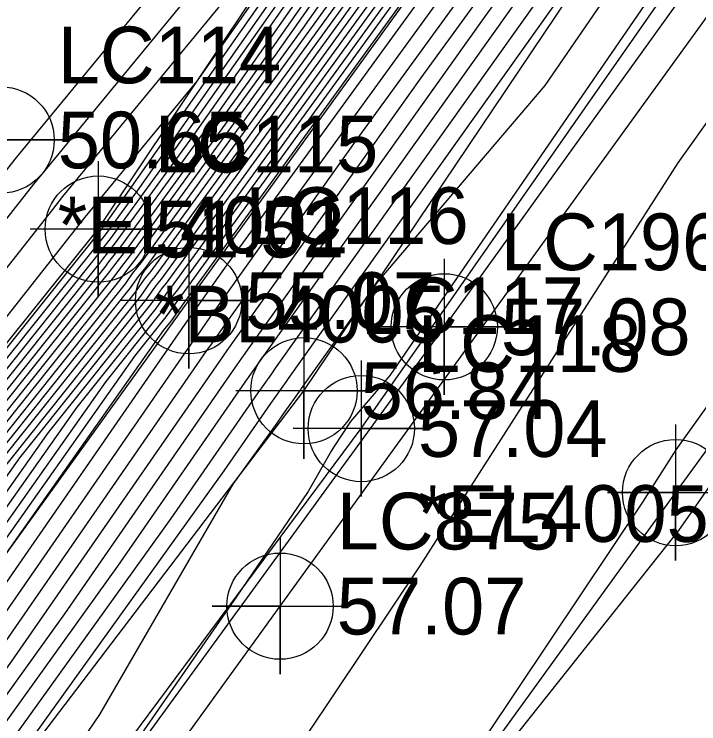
# Model space of a CAD drawing. Extents: x 2188792 to 2191981, y 386090 to 389710.
# Drawn here: x 2190020.33 to 2190050.53, y 387484.06 to 387515.36 of the extents above; entities that cross this region are included whole.
import ezdxf

# ---------------------------------------------------------------- set-up
doc = ezdxf.new("R2010")
doc.units = 0
for name, color, linetype in [('DTM Contours Major', 7, 'Continuous'), ('DTM Contours Minor', 7, 'Continuous'), ('Exist DTM Breakline', 7, 'Continuous'), ('Exist DTM Breakline Cogo Comment', 7, 'Continuous'), ('Exist DTM Breakline Cogo Elevation', 7, 'Continuous'), ('Exist DTM Breakline Cogo Number', 7, 'Continuous'), ('Exist DTM Breakline Cogo Point CELL', 7, 'Continuous'), ('Exist DTM Regular Point Underwater CELL', 7, 'Continuous'), ('Exist DTM Regular Point Underwater Cogo Comment', 7, 'Continuous'), ('Exist DTM Regular Point Underwater Cogo Elevation', 7, 'Continuous'), ('Exist DTM Regular Point Underwater Cogo Number', 7, 'Continuous'), ('Exist Roads EOP', 7, 'Continuous'), ('Exist Roads EOP Cogo Elevation', 7, 'Continuous'), ('Exist Roads EOP Cogo Number', 7, 'Continuous'), ('Exist Roads EOP Cogo Point CELL', 7, 'Continuous'), ('Exist Roads EOT', 7, 'Continuous'), ('Exist Roads EOT Cogo Elevation', 7, 'Continuous'), ('Exist Roads EOT Cogo Number', 7, 'Continuous'), ('Exist Roads EOT Cogo Point CELL', 7, 'Continuous')]:
    doc.layers.add(name, color=color, linetype=linetype)

msp = doc.modelspace()

# ---------------------------------------------------------------- linework, layer by layer
at = {"layer": 'DTM Contours Major'}
for points in [[(2189984.352, 387440.029), (2189988.632, 387446.331), (2189991.161, 387450.388), (2189992.862, 387452.939), (2190007.704, 387474.081), (2190010.026, 387477.237), (2190010.866, 387478.407), (2190020.031, 387491.642), (2190026.918, 387501.402), (2190027.261, 387501.831), (2190027.928, 387502.771), (2190027.942, 387502.789), (2190045.269, 387526.683), (2190045.546, 387527.079), (2190062.971, 387551.105)], [(2189957.921, 387412.608), (2189960.495, 387415.615), (2189963.565, 387419.576), (2189966.033, 387422.473), (2189971.823, 387427.618), (2189973.953, 387429.864), (2189975.86, 387430.935), (2189976.679, 387433.44), (2189978.768, 387435.688), (2189981.855, 387440.257), (2189983.77, 387442.845), (2189986.732, 387447.206), (2189989.796, 387452.121), (2189990.78, 387454.257), (2190003.512, 387472.407), (2190008.404, 387478.538), (2190020.573, 387495.783), (2190026.132, 387502.74), (2190026.608, 387503.41), (2190026.821, 387503.676), (2190039.173, 387520.711), (2190044.314, 387528.031), (2190057.303, 387545.941)], [(2189957.493, 387397.732), (2189959.964, 387401.028), (2189969.853, 387414.121), (2189972.085, 387417.1), (2189976.117, 387420.341), (2189977.065, 387420.694), (2189985.076, 387432.063), (2189985.095, 387433.258), (2189987.112, 387436.647), (2189989.644, 387440.904), (2189993.471, 387446.692), (2189993.574, 387448.499), (2189995.205, 387451.102), (2190002.478, 387461.302), (2190012.599, 387475.058), (2190022.556, 387488.916), (2190029.949, 387499.592), (2190030.371, 387500.182), (2190030.688, 387500.641), (2190041.096, 387515.254), (2190048.167, 387524.986), (2190060.341, 387542.129)], [(2190065.584, 387541.202), (2190052.374, 387521.969), (2190036.892, 387499.429), (2190035.158, 387497.397), (2190034.428, 387496.276), (2190034.315, 387496.082), (2190033.287, 387494.306), (2190030.14, 387489.689), (2190021.316, 387476.946), (2190020.217, 387475.365), (2190016.872, 387468.628), (2190016.421, 387467.617), (2190003.679, 387446.83), (2190000.724, 387442.025), (2189990.894, 387427.571), (2189987.772, 387422.404), (2189976.242, 387405.344), (2189970.251, 387398.185), (2189960.836, 387388.027), (2189958.804, 387385.627)], [(2189955.068, 387412.785), (2189960.286, 387418.879), (2189961.085, 387419.91), (2189965.998, 387425.677), (2189967.889, 387427.358), (2189972.645, 387432.374), (2189973.523, 387432.867), (2189973.901, 387434.022), (2189978.006, 387438.439), (2189979.705, 387440.954), (2189983.189, 387445.661), (2189984.832, 387448.081), (2189986.532, 387450.808), (2189988.83, 387455.794), (2189996.597, 387466.866), (2190006.879, 387479.75), (2190014.228, 387490.164), (2190025.003, 387503.648), (2190025.288, 387504.048), (2190025.699, 387504.563), (2190033.078, 387514.739), (2190043.082, 387528.982), (2190051.636, 387540.776)], [(2189957.168, 387450.113), (2189962.705, 387455.58), (2189963.359, 387456.976), (2189968.321, 387461.932), (2189971.382, 387462.319), (2189982.029, 387462.255), (2189993.359, 387476.866), (2189994.6, 387481.754), (2189995.932, 387520.719), (2190013.29, 387497.82), (2190021.199, 387507.858), (2190021.483, 387508.219), (2190037.161, 387527.264), (2190028.053, 387532.529), (2190026.213, 387539.316)], [(2189953.618, 387431.202), (2189959.565, 387434.157), (2189961.984, 387436.074), (2189969.442, 387436.668), (2189973.707, 387437.385), (2189977.243, 387441.19), (2189977.555, 387441.65), (2189982.607, 387448.477), (2189982.933, 387448.956), (2189983.269, 387449.495), (2189986.88, 387457.33), (2189989.682, 387461.324), (2190005.354, 387480.961), (2190007.883, 387484.545), (2190023.875, 387504.556), (2190023.967, 387504.687), (2190024.577, 387505.45), (2190026.983, 387508.767), (2190041.85, 387529.933), (2190045.968, 387535.612)]]:
    msp.add_lwpolyline(points, dxfattribs=at)
at = {"layer": 'DTM Contours Minor'}
for points in [[(2189958.048, 387448.514), (2189959.221, 387449.811), (2189963.913, 387454.444), (2189963.96, 387454.544), (2189969.838, 387460.415), (2189970.296, 387460.473), (2189983.751, 387460.392), (2189998.07, 387478.857), (2189998.788, 387481.688), (2189999.56, 387504.257), (2190009.614, 387490.994), (2190022.026, 387506.747), (2190022.471, 387507.313), (2190035.891, 387523.615), (2190040.864, 387530.695), (2190041.434, 387531.48), (2190058.134, 387555.179)], [(2189955.119, 387438.452), (2189959.956, 387442.286), (2189963.705, 387442.584), (2189971.264, 387443.854), (2189972.973, 387445.744), (2189977.203, 387450.649), (2189978.807, 387452.419), (2189984.064, 387453.528), (2189986.1, 387457.945), (2189986.916, 387459.108), (2190004.744, 387481.446), (2190005.345, 387482.298), (2190023.423, 387504.92), (2190023.439, 387504.943), (2190024.129, 387505.805), (2190024.545, 387506.379), (2190041.357, 387530.314), (2190043.701, 387533.546), (2190058.663, 387554.778)], [(2189958.943, 387445.392), (2189960.837, 387445.543), (2189964.656, 387446.184), (2189968.309, 387450.223), (2189970.339, 387452.577), (2189974.036, 387456.657), (2189982.989, 387458.545), (2189985.473, 387458.53), (2190002.78, 387480.847), (2190002.977, 387481.622), (2190003.188, 387487.795), (2190005.938, 387484.167), (2190022.852, 387505.635), (2190023.46, 387506.407), (2190028.397, 387512.404), (2190041.111, 387530.504), (2190042.568, 387532.513), (2190058.398, 387554.979)], [(2189957.342, 387436.305), (2189960.97, 387439.18), (2189966.574, 387439.626), (2189976.709, 387441.329), (2189977.091, 387441.74), (2189977.125, 387441.79), (2189982.491, 387449.04), (2189982.553, 387449.13), (2189982.616, 387449.233), (2189986.49, 387457.637), (2189988.299, 387460.216), (2190005.049, 387481.204), (2190006.614, 387483.421), (2190023.649, 387504.738), (2190023.703, 387504.815), (2190024.353, 387505.628), (2190025.764, 387507.573), (2190041.603, 387530.124), (2190044.835, 387534.579), (2190058.927, 387554.577)], [(2189955.308, 387371.872), (2189966.747, 387385.386), (2189969.936, 387388.826), (2189985.972, 387407.987), (2189987.388, 387410.082), (2189997.235, 387426.377), (2190000.201, 387430.738), (2190011.219, 387448.654), (2190017.983, 387459.688), (2190025.097, 387470.227), (2190031.989, 387481.689), (2190038.237, 387491.023), (2190049.61, 387508.8), (2190053.061, 387513.633), (2190063.181, 387529.704), (2190065.491, 387532.944), (2190080.791, 387553.075)], [(2189955.863, 387403.686), (2189960.537, 387409.923), (2189962.716, 387412.808), (2189967.226, 387418.828), (2189975.374, 387425.378), (2189977.291, 387426.092), (2189980.462, 387430.593), (2189980.5, 387432.909), (2189983.924, 387438.665), (2189984.435, 387439.422), (2189984.468, 387439.466), (2189989.012, 387446.156), (2189990.295, 387448.214), (2189993.358, 387452.805), (2190003.177, 387466.793), (2190010.541, 387476.802), (2190013.204, 387480.508), (2190027.711, 387501.458), (2190027.772, 387501.543), (2190028.391, 387502.438), (2190029.827, 387504.455), (2190046.003, 387526.716), (2190047.848, 387529.313), (2190063.603, 387551)], [(2189956.27, 387402.198), (2189960.394, 387407.699), (2189964.5, 387413.136), (2189968.441, 387418.396), (2189975.56, 387424.119), (2189977.234, 387424.742), (2189981.616, 387430.96), (2189981.649, 387432.997), (2189985.085, 387438.773), (2189989.245, 387445.764), (2189989.392, 387445.981), (2189989.429, 387446.041), (2189993.853, 387452.672), (2189998.65, 387459.506), (2190011.055, 387476.366), (2190015.542, 387482.61), (2190028.271, 387500.992), (2190028.421, 387501.203), (2190028.965, 387501.988), (2190032.644, 387507.154), (2190046.544, 387526.283), (2190050.971, 387532.517), (2190064.1, 387550.59)], [(2189984.235, 387440.592), (2189988.252, 387446.506), (2189992.027, 387452.562), (2189992.367, 387453.072), (2189997.801, 387460.812), (2190009.043, 387476.841), (2190009.625, 387477.569), (2190025.649, 387500.279), (2190027.035, 387502.013), (2190027.664, 387502.899), (2190027.718, 387502.967), (2190044.05, 387525.489), (2190045.3, 387527.269), (2190061.837, 387550.072)], [(2189955.19, 387406.762), (2189959.632, 387412.503), (2189960.621, 387413.657), (2189965.053, 387419.376), (2189966.055, 387420.551), (2189974.184, 387427.774), (2189974.737, 387428.358), (2189977.262, 387429.776), (2189978.346, 387433.091), (2189979.225, 387434.037), (2189983.145, 387439.839), (2189984.119, 387441.155), (2189987.872, 387446.681), (2189991.754, 387452.908), (2189991.95, 387453.335), (2190007.66, 387475.732), (2190009.32, 387477.811), (2190024.38, 387499.155), (2190026.81, 387502.195), (2190027.4, 387503.027), (2190027.494, 387503.144), (2190042.83, 387524.295), (2190045.054, 387527.46), (2190060.704, 387549.039)], [(2190066.588, 387548.537), (2190049.25, 387524.121), (2190046.73, 387520.654), (2190031.837, 387499.742), (2190031.67, 387499.501), (2190031.068, 387498.659), (2190027.232, 387493.119), (2190013.629, 387474.186), (2190010.451, 387469.867), (2190000.703, 387456.196), (2189998.289, 387452.392), (2189996.348, 387449.596), (2189996.21, 387447.174), (2189989.807, 387437.489), (2189988.463, 387435.23), (2189987.393, 387433.432), (2189987.383, 387432.798), (2189976.952, 387417.995), (2189976.488, 387417.822), (2189974.514, 387416.236), (2189973.422, 387414.778), (2189959.678, 387396.581), (2189958.309, 387394.755)], [(2189955.108, 387407.428), (2189959.062, 387412.538), (2189960.579, 387414.31), (2189964.557, 387419.443), (2189966.047, 387421.192), (2189973.397, 387427.722), (2189974.476, 387428.86), (2189976.795, 387430.162), (2189977.791, 387433.208), (2189979.072, 387434.587), (2189982.715, 387439.979), (2189984.003, 387441.719), (2189987.492, 387446.856), (2189991.101, 387452.646), (2189991.56, 387453.643), (2190006.277, 387474.624), (2190009.014, 387478.054), (2190023.111, 387498.031), (2190026.584, 387502.376), (2190027.136, 387503.154), (2190027.269, 387503.321), (2190041.611, 387523.1), (2190044.807, 387527.65), (2190059.57, 387548.006)], [(2190067.418, 387547.671), (2190051.466, 387526.048), (2190049.791, 387523.688), (2190049.547, 387523.353), (2190032.412, 387499.293), (2190032.32, 387499.161), (2190031.628, 387498.193), (2190029.57, 387495.221), (2190015.34, 387475.415), (2190014.879, 387474.621), (2190014.239, 387473.68), (2190005.531, 387459.96), (2189997.647, 387448.599), (2189997.579, 387447.415), (2189989.888, 387435.781), (2189989.138, 387434.522), (2189988.542, 387433.519), (2189988.536, 387433.165), (2189976.896, 387416.646), (2189976.674, 387416.563), (2189975.729, 387415.804), (2189975.206, 387415.106), (2189959.534, 387394.357), (2189958.717, 387393.266)], [(2189958.491, 387412.573), (2189960.537, 387414.962), (2189964.061, 387419.509), (2189966.04, 387421.833), (2189972.61, 387427.67), (2189974.214, 387429.362), (2189976.327, 387430.549), (2189977.235, 387433.324), (2189978.92, 387435.137), (2189982.285, 387440.118), (2189983.887, 387442.282), (2189987.112, 387447.031), (2189990.448, 387452.383), (2189991.17, 387453.95), (2190004.894, 387473.516), (2190008.709, 387478.296), (2190021.842, 387496.907), (2190026.358, 387502.558), (2190026.872, 387503.282), (2190027.045, 387503.499), (2190040.392, 387521.906), (2190044.561, 387527.84), (2190058.437, 387546.974)], [(2190068.248, 387546.805), (2190057.272, 387531.926), (2190051.04, 387522.853), (2190043.736, 387512.22), (2190036.345, 387503.56), (2190032.986, 387498.844), (2190032.97, 387498.82), (2190032.188, 387497.726), (2190031.908, 387497.323), (2190029.977, 387494.635), (2190024.083, 387484.464), (2190015.878, 387472.42), (2190012.773, 387467.529), (2190000.192, 387449.398), (2189999.383, 387448.234), (2189997.616, 387445.64), (2189989.969, 387434.074)], [(2189957.901, 387396.243), (2189959.821, 387398.805), (2189971.637, 387414.449), (2189973.299, 387416.668), (2189976.302, 387419.082), (2189977.009, 387419.345), (2189986.229, 387432.43), (2189986.244, 387433.345), (2189987.787, 387435.939), (2189989.725, 387439.197), (2189994.84, 387446.933), (2189994.978, 387449.349), (2189995.635, 387450.396), (2190006.465, 387465.585), (2190013.114, 387474.622), (2190024.894, 387491.018), (2190030.509, 387499.126), (2190031.021, 387499.841), (2190031.263, 387500.191), (2190043.913, 387517.954), (2190048.709, 387524.553), (2190063.465, 387545.333)], [(2189957.35, 387412.644), (2189960.453, 387416.268), (2189963.069, 387419.643), (2189966.026, 387423.114), (2189971.037, 387427.566), (2189973.691, 387430.366), (2189975.393, 387431.321), (2189976.124, 387433.557), (2189978.615, 387436.238), (2189981.425, 387440.397), (2189983.654, 387443.408), (2189986.352, 387447.381), (2189989.143, 387451.858), (2189990.39, 387454.565), (2190002.129, 387471.299), (2190008.099, 387478.781), (2190019.304, 387494.66), (2190025.906, 387502.921), (2190026.344, 387503.538), (2190026.596, 387503.854), (2190037.954, 387519.517), (2190044.068, 387528.221), (2190056.17, 387544.908)], [(2189956.78, 387412.679), (2189960.412, 387416.92), (2189962.573, 387419.71), (2189966.019, 387423.755), (2189970.25, 387427.514), (2189973.429, 387430.868), (2189974.925, 387431.708), (2189975.568, 387433.673), (2189978.463, 387436.788), (2189980.995, 387440.536), (2189983.538, 387443.971), (2189985.972, 387447.556), (2189988.49, 387451.595), (2189990, 387454.872), (2190000.746, 387470.191), (2190007.794, 387479.023), (2190018.035, 387493.536), (2190025.681, 387503.103), (2190026.08, 387503.665), (2190026.372, 387504.031), (2190036.735, 387518.323), (2190043.821, 387528.411), (2190055.036, 387543.875)], [(2189956.209, 387412.714), (2189960.37, 387417.573), (2189962.077, 387419.776), (2189966.012, 387424.396), (2189969.463, 387427.462), (2189973.168, 387431.37), (2189974.458, 387432.094), (2189975.012, 387433.789), (2189978.31, 387437.338), (2189980.565, 387440.675), (2189983.421, 387444.534), (2189985.592, 387447.731), (2189987.838, 387451.333), (2189989.61, 387455.179), (2189999.363, 387469.082), (2190007.489, 387479.265), (2190016.766, 387492.412), (2190025.455, 387503.285), (2190025.816, 387503.793), (2190026.148, 387504.208), (2190035.516, 387517.128), (2190043.575, 387528.601), (2190053.903, 387542.842)], [(2189955.639, 387412.749), (2189960.328, 387418.226), (2189961.581, 387419.843), (2189966.005, 387425.036), (2189968.676, 387427.41), (2189972.906, 387431.872), (2189973.991, 387432.481), (2189974.457, 387433.906), (2189978.158, 387437.888), (2189980.135, 387440.815), (2189983.305, 387445.098), (2189985.212, 387447.906), (2189987.185, 387451.07), (2189989.22, 387455.486), (2189997.98, 387467.974), (2190007.184, 387479.507), (2190015.497, 387491.288), (2190025.229, 387503.466), (2190025.552, 387503.921), (2190025.923, 387504.386), (2190034.297, 387515.934), (2190043.329, 387528.792), (2190052.769, 387541.809)], [(2189954.498, 387412.82), (2189960.244, 387419.531), (2189960.589, 387419.977), (2189965.991, 387426.318), (2189967.102, 387427.306), (2189972.383, 387432.876), (2189973.056, 387433.254), (2189973.345, 387434.138), (2189977.853, 387438.989), (2189979.275, 387441.093), (2189983.073, 387446.224), (2189984.452, 387448.256), (2189985.88, 387450.545), (2189988.44, 387456.101), (2189995.214, 387465.757), (2190006.574, 387479.992), (2190012.959, 387489.04), (2190024.778, 387503.83), (2190025.024, 387504.176), (2190025.475, 387504.741), (2190031.859, 387513.545), (2190042.836, 387529.172), (2190050.502, 387539.743)], [(2189957.086, 387399.221), (2189960.107, 387403.252), (2189968.069, 387413.793), (2189970.87, 387417.532), (2189975.931, 387421.6), (2189977.121, 387422.044), (2189983.922, 387431.695), (2189983.946, 387433.171), (2189986.436, 387437.356), (2189989.563, 387442.612), (2189992.101, 387446.451), (2189992.17, 387447.65), (2189994.776, 387451.808), (2189998.492, 387457.02), (2190012.085, 387475.494), (2190020.218, 387486.814), (2190029.39, 387500.059), (2190029.721, 387500.522), (2190030.114, 387501.09), (2190038.279, 387512.554), (2190047.626, 387525.418), (2190057.218, 387538.925)], [(2189954.865, 387418.975), (2189959.208, 387421.109), (2189960.948, 387421.931), (2189962.292, 387422.624), (2189965.984, 387426.959), (2189966.316, 387427.254), (2189972.121, 387433.378), (2189972.589, 387433.64), (2189972.79, 387434.255), (2189977.701, 387439.539), (2189978.845, 387441.233), (2189982.956, 387446.787), (2189984.072, 387448.431), (2189985.227, 387450.283), (2189988.05, 387456.408), (2189993.831, 387464.649), (2190006.269, 387480.234), (2190011.69, 387487.917), (2190024.552, 387504.011), (2190024.76, 387504.304), (2190025.25, 387504.918), (2190030.64, 387512.351), (2190042.589, 387529.363), (2190049.369, 387538.711)], [(2189955.245, 387425.507), (2189964.012, 387429.863), (2189967.704, 387429.496), (2189971.86, 387433.88), (2189972.122, 387434.027), (2189972.234, 387434.371), (2189977.548, 387440.089), (2189978.415, 387441.372), (2189982.84, 387447.35), (2189983.693, 387448.606), (2189984.574, 387450.02), (2189987.66, 387456.716), (2189992.448, 387463.541), (2190005.964, 387480.477), (2190010.421, 387486.793), (2190024.326, 387504.193), (2190024.496, 387504.432), (2190025.026, 387505.096), (2190029.421, 387511.156), (2190042.343, 387529.553), (2190048.235, 387537.678)], [(2189956.413, 387451.696), (2189961.497, 387456.716), (2189962.758, 387459.408), (2189966.804, 387463.449), (2189972.468, 387464.164), (2189980.307, 387464.117), (2189988.649, 387474.875), (2189990.412, 387481.82), (2189992.305, 387537.181), (2190016.966, 387504.647), (2190020.372, 387508.97), (2190020.495, 387509.125), (2190027.247, 387517.328), (2189992.67, 387537.316)], [(2190078.772, 387537.414), (2190063.592, 387516.122), (2190062.167, 387513.859), (2190049.516, 387496.136), (2190048.045, 387493.838), (2190034.215, 387473.177), (2190049.645, 387492.586), (2190050.943, 387494.441), (2190063.751, 387512.041), (2190065.514, 387514.559), (2190081.303, 387536.264)], [(2189954.431, 387428.355), (2189961.788, 387432.01), (2189962.998, 387432.969), (2189969.913, 387433.519), (2189970.706, 387433.44), (2189971.598, 387434.382), (2189971.654, 387434.413), (2189971.678, 387434.487), (2189977.396, 387440.64), (2189977.985, 387441.511), (2189982.724, 387447.913), (2189983.313, 387448.781), (2189983.922, 387449.758), (2189987.27, 387457.023), (2189991.065, 387462.433), (2190005.659, 387480.719), (2190009.152, 387485.669), (2190024.1, 387504.375), (2190024.231, 387504.559), (2190024.802, 387505.273), (2190028.202, 387509.962), (2190042.096, 387529.743), (2190047.102, 387536.645)], [(2189956.678, 387400.709), (2189960.251, 387405.476), (2189966.285, 387413.464), (2189969.655, 387417.964), (2189975.746, 387422.859), (2189977.178, 387423.393), (2189982.769, 387431.328), (2189982.798, 387433.084), (2189985.761, 387438.064), (2189989.482, 387444.319), (2189990.732, 387446.21), (2189990.766, 387446.8), (2189994.346, 387452.513), (2189994.505, 387452.737), (2190011.57, 387475.93), (2190017.88, 387484.712), (2190028.83, 387500.525), (2190029.071, 387500.862), (2190029.54, 387501.539), (2190035.462, 387509.854), (2190047.085, 387525.851), (2190054.095, 387535.721)]]:
    msp.add_lwpolyline(points, dxfattribs=at)
at = {"layer": 'Exist DTM Breakline'}
for points in [[(2189985.78, 387458.197), (2190024.035, 387505.879), (2190058.15, 387556.911), (2190090.329, 387601.585), (2190123.453, 387645.538), (2190155.634, 387692.318), (2190180.541, 387728.105)], [(2189992.243, 387453.105), (2190028.023, 387502.725), (2190063.31, 387551.461), (2190096.85, 387598.566), (2190127.537, 387642.384), (2190160.72, 387688.44), (2190186.991, 387724.396)], [(2189995.924, 387449.921), (2190033.109, 387498.748), (2190066.603, 387548.559), (2190100.696, 387595.155), (2190131.134, 387639.583), (2190163.791, 387685.951), (2190192.781, 387722.608)], [(2189998.889, 387447.645), (2190035.636, 387497.082), (2190069.466, 387545.534), (2190104.367, 387592.678), (2190135.108, 387636.538), (2190168.392, 387682.449), (2190194.386, 387718.656)]]:
    msp.add_lwpolyline(points, dxfattribs=at)
at = {"layer": 'Exist DTM Breakline Cogo Point CELL'}
for points in [[(2190024.035, 387508.879), (2190024.035, 387502.879), (2190024.035, 387505.879), (2190027.035, 387505.879), (2190021.035, 387505.879)], [(2190028.023, 387505.725), (2190028.023, 387499.725), (2190028.023, 387502.725), (2190031.023, 387502.725), (2190025.023, 387502.725)], [(2190033.109, 387501.748), (2190033.109, 387495.748), (2190033.109, 387498.748), (2190036.109, 387498.748), (2190030.109, 387498.748)], [(2190035.636, 387500.082), (2190035.636, 387494.082), (2190035.636, 387497.082), (2190038.636, 387497.082), (2190032.636, 387497.082)]]:
    msp.add_lwpolyline(points, dxfattribs=at)
for centre in [(2190024.035, 387505.879), (2190028.023, 387502.725), (2190033.109, 387498.748), (2190035.636, 387497.082)]:
    msp.add_circle(centre, 2.344, dxfattribs=at)
at = {"layer": 'Exist DTM Regular Point Underwater CELL'}
msp.add_lwpolyline([(2190019.747, 387512.811), (2190019.747, 387506.811), (2190019.747, 387509.811), (2190022.747, 387509.811), (2190016.747, 387509.811)], dxfattribs=at)
msp.add_circle((2190019.747, 387509.811), 2.344, dxfattribs=at)
at = {"layer": 'Exist Roads EOP'}
msp.add_lwpolyline([(2190313.986, 387884.141), (2190285.547, 387843.636), (2190254.588, 387800.045), (2190225.155, 387759.32), (2190194.829, 387717.425), (2190164.291, 387675.101), (2190137.229, 387637.301), (2190105.098, 387592.774), (2190071.411, 387546.221), (2190039.296, 387501.568), (2190007.542, 387457.958), (2189976.844, 387415.407), (2189936.359, 387359.145), (2189907.138, 387318.716), (2189868.636, 387265.243), (2189836.428, 387220.463), (2189805.695, 387177.815), (2189775.592, 387135.957), (2189745.498, 387094.055), (2189715.496, 387052.249), (2189683.869, 387008.07), (2189653.218, 386965.867), (2189623.729, 386924.667)], dxfattribs=at)
at = {"layer": 'Exist Roads EOP Cogo Point CELL'}
msp.add_lwpolyline([(2190039.296, 387504.568), (2190039.296, 387498.568), (2190039.296, 387501.568), (2190042.296, 387501.568), (2190036.296, 387501.568)], dxfattribs=at)
msp.add_circle((2190039.296, 387501.568), 2.344, dxfattribs=at)
at = {"layer": 'Exist Roads EOT'}
for points in [[(2189910.407, 387320.236), (2189942.075, 387364.22), (2189970.438, 387403.768), (2190000.916, 387446.161), (2190032.053, 387489.248), (2190063.107, 387532.142), (2190093.978, 387574.79), (2190125.104, 387617.946), (2190155.102, 387659.638), (2190185.949, 387702.484), (2190216.886, 387745.11), (2190247.602, 387787.3), (2190276.876, 387828.015), (2190303.928, 387865.67), (2190323.039, 387892.195)], [(2190174.375, 387667.889), (2190147.471, 387630.495), (2190115.247, 387585.778), (2190081.202, 387538.232), (2190049.502, 387494.256), (2190017.538, 387450.182), (2189987.334, 387408.357), (2189946.666, 387352.019), (2189917.402, 387311.129), (2189878.955, 387257.772), (2189846.565, 387212.819), (2189815.837, 387170.306), (2189785.374, 387128.351), (2189755.717, 387086.921), (2189724.953, 387044.041), (2189693.727, 387000.805), (2189663.933, 386959.217), (2189633.425, 386917.196)]]:
    msp.add_lwpolyline(points, dxfattribs=at)
at = {"layer": 'Exist Roads EOT Cogo Point CELL'}
for points in [[(2190049.502, 387497.256), (2190049.502, 387491.256), (2190049.502, 387494.256), (2190046.502, 387494.256), (2190052.502, 387494.256)], [(2190032.053, 387492.248), (2190032.053, 387486.248), (2190032.053, 387489.248), (2190029.053, 387489.248), (2190035.053, 387489.248)]]:
    msp.add_lwpolyline(points, dxfattribs=at)
for centre in [(2190049.502, 387494.256), (2190032.053, 387489.248)]:
    msp.add_circle(centre, 2.344, dxfattribs=at)

# ---------------------------------------------------------------- texts
at = {"layer": 'Exist DTM Breakline Cogo Comment'}
for s, p in [('*BL4005', (2190026.535, 387500.879)), ('*EL4005', (2190038.136, 387492.082))]:
    msp.add_text(s, height=2.5, dxfattribs=at).set_placement(p)
at = {"layer": 'Exist DTM Breakline Cogo Elevation'}
for s, p in [('51.52', (2190026.535, 387504.629)), ('55.07', (2190030.523, 387501.475)), ('56.84', (2190035.609, 387497.498)), ('57.04', (2190038.136, 387495.832))]:
    msp.add_text(s, height=2.5, dxfattribs=at).set_placement(p)
at = {"layer": 'Exist DTM Breakline Cogo Number'}
for s, p in [('LC115', (2190026.535, 387508.379)), ('LC116', (2190030.523, 387505.225)), ('LC117', (2190035.609, 387501.248)), ('LC118', (2190038.136, 387499.582))]:
    msp.add_text(s, height=2.5, dxfattribs=at).set_placement(p)
at = {"layer": 'Exist DTM Regular Point Underwater Cogo Comment'}
msp.add_text('*EL4001', height=2.5, dxfattribs=at).set_placement((2190022.247, 387504.811))
at = {"layer": 'Exist DTM Regular Point Underwater Cogo Elevation'}
msp.add_text('50.65', height=2.5, dxfattribs=at).set_placement((2190022.247, 387508.561))
at = {"layer": 'Exist DTM Regular Point Underwater Cogo Number'}
msp.add_text('LC114', height=2.5, dxfattribs=at).set_placement((2190022.247, 387512.311))
at = {"layer": 'Exist Roads EOP Cogo Elevation'}
msp.add_text('57.08', height=2.5, dxfattribs=at).set_placement((2190041.796, 387500.318))
at = {"layer": 'Exist Roads EOP Cogo Number'}
msp.add_text('LC196', height=2.5, dxfattribs=at).set_placement((2190041.796, 387504.068))
at = {"layer": 'Exist Roads EOT Cogo Elevation'}
msp.add_text('57.07', height=2.5, dxfattribs=at).set_placement((2190034.553, 387487.998))
at = {"layer": 'Exist Roads EOT Cogo Number'}
msp.add_text('LC875', height=2.5, dxfattribs=at).set_placement((2190034.553, 387491.748))

doc.saveas('drawing.dxf')
